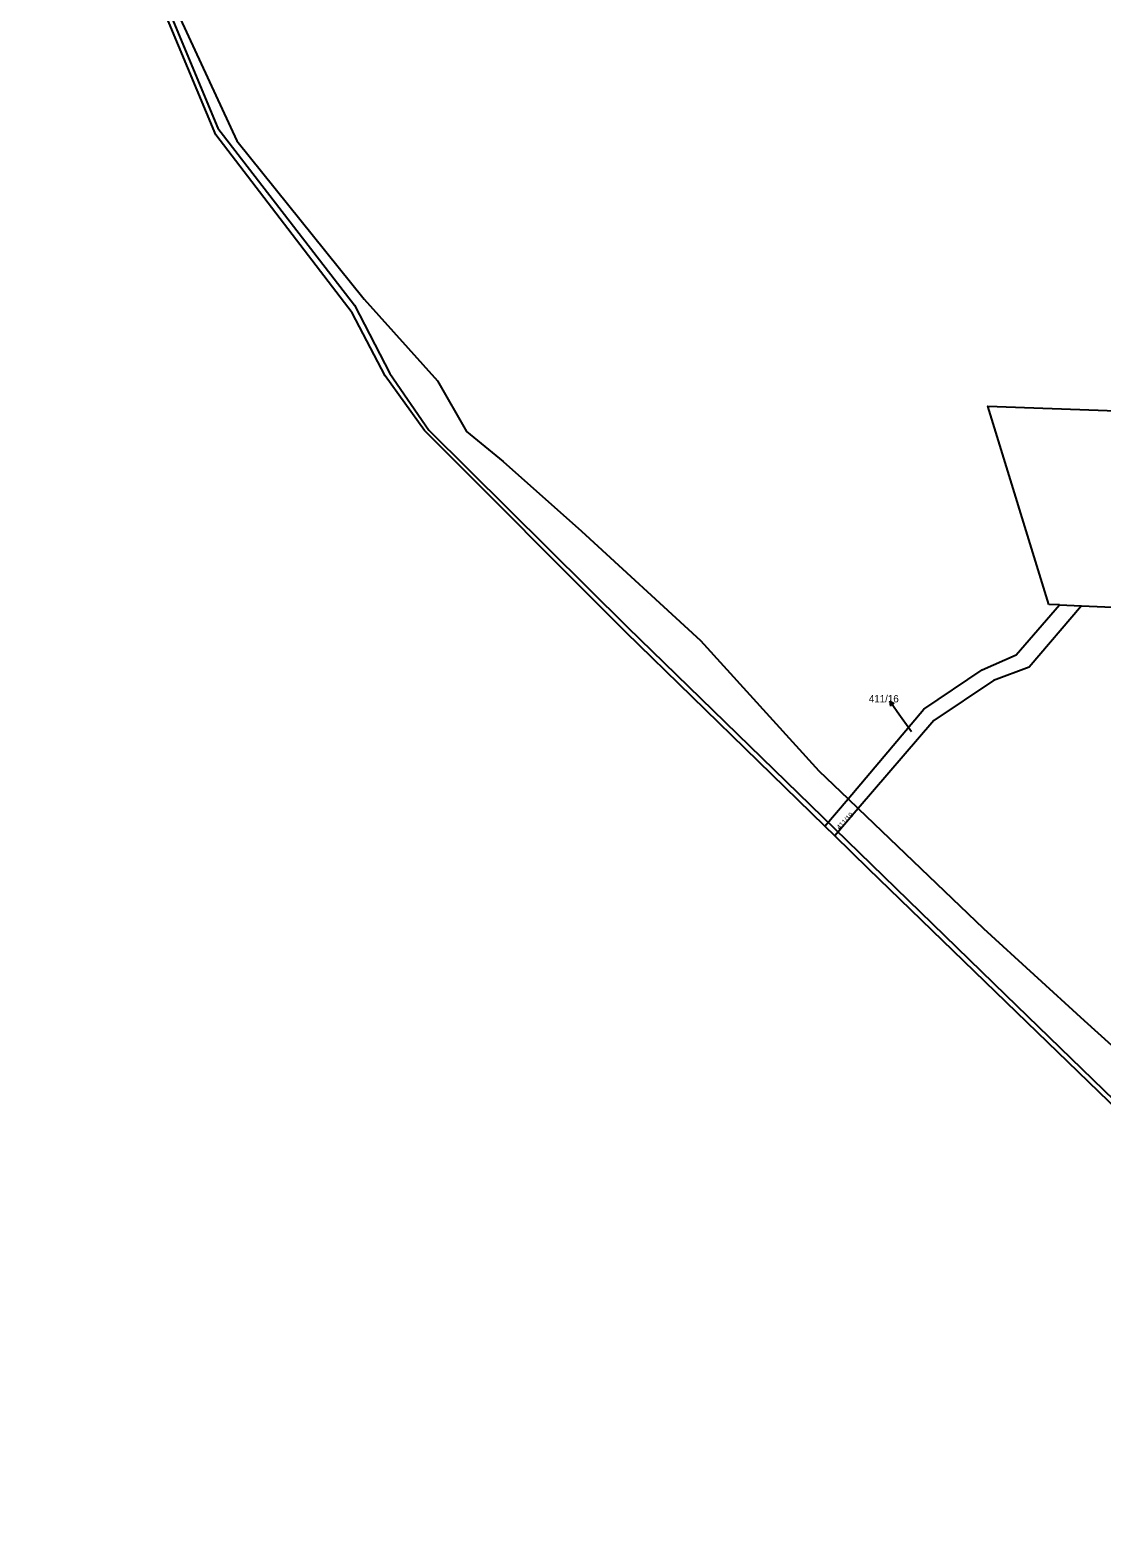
# Model space of a CAD drawing. Extents: x -880531 to -877616, y -1023932 to -1021350.
# Drawn here: x -880530.7 to -880281.2, y -1022570 to -1022219 of the extents above; entities that cross this region are included whole.
import ezdxf

# ---------------------------------------------------------------- set-up
doc = ezdxf.new("R2010")
doc.units = 0
for name, color, linetype in [('Hranice parcel', 7, 'Continuous'), ('Parcelní čísla', 7, 'Continuous'), ('Pop  PČ popisy', 7, 'Continuous'), ('Vnitřní kresba', 7, 'Continuous')]:
    doc.layers.add(name, color=color, linetype=linetype)

msp = doc.modelspace()

# ---------------------------------------------------------------- linework, layer by layer
at = {"layer": 'Hranice parcel'}
for p, q in [((-880391.99, -1022359.17), (-880438.9, -1022312.23)), ((-880291.06, -1022352.79), (-880293.53, -1022352.68)), ((-880291.06, -1022352.79), (-880285.88, -1022353.02)), ((-880285.88, -1022353.02), (-880196.77, -1022357.04)), ((-880345.66, -1022404.32), (-880391.99, -1022359.17)), ((-880347.08, -1022391.39), (-880340.26, -1022397.94)), ((-880345.66, -1022404.32), (-880340.26, -1022397.94)), ((-880337.9, -1022400.2), (-880343.36, -1022406.56)), ((-880340.26, -1022397.94), (-880337.9, -1022400.2)), ((-880337.9, -1022400.2), (-880308.75, -1022428.16)), ((-880343.36, -1022406.56), (-880345.66, -1022404.32)), ((-880335.48, -1022414.24), (-880343.36, -1022406.56))]:
    msp.add_line(p, q, dxfattribs=at)
for points in [[(-880438.9, -1022312.23), (-880448.03, -1022299.45), (-880455.75, -1022284.78), (-880487.48, -1022243.34), (-880524.79, -1022153.92), (-880529.34, -1022124.84), (-880530.7, -1022098.83), (-880528.56, -1022064.4), (-880524.89, -1022050.76), (-880519.28, -1022036.32), (-880479.95, -1021972.5), (-880463.94, -1021954.07), (-880458.37, -1021949.23)], [(-880452.22, -1021959.53), (-880469.68, -1021977.36), (-880478.53, -1021984.54), (-880491.76, -1022000.43), (-880511.96, -1022039.42), (-880517.25, -1022057.99), (-880520.93, -1022084.07), (-880523.46, -1022123.46), (-880519.31, -1022152.85), (-880508.5, -1022183.09), (-880495.79, -1022216.24), (-880482.58, -1022244.73), (-880452.91, -1022281.59), (-880435.85, -1022300.63), (-880429.09, -1022312.44), (-880420.6, -1022319.4), (-880402.34, -1022335.61), (-880374.63, -1022361.05), (-880347.08, -1022391.39)], [(-880293.53, -1022352.68), (-880307.71, -1022306.49), (-880237.11, -1022309.12), (-880176.85, -1022311.48)], [(-880340.26, -1022397.94), (-880322.65, -1022377.1), (-880309.06, -1022367.89), (-880301.11, -1022364.45), (-880291.06, -1022352.79)], [(-880285.88, -1022353.02), (-880298.14, -1022367.3), (-880306.43, -1022370.4), (-880320.3, -1022379.73), (-880337.9, -1022400.2)], [(-880234.6, -1022570), (-880234.38, -1022561.23), (-880236.2, -1022545.85), (-880242.27, -1022523.44), (-880253.08, -1022500.29), (-880261.13, -1022488.37), (-880272.31, -1022475.43), (-880300.95, -1022447.69), (-880335.48, -1022414.24)], [(-880308.75, -1022428.16), (-880285.32, -1022449.52), (-880263.77, -1022468.93), (-880224.44, -1022487.13), (-880146.12, -1022501.79)]]:
    msp.add_lwpolyline(points, dxfattribs=at)
at = {"layer": 'Pop  PČ popisy'}
for p, q in [((-880328.81, -1022377.7), (-880330.531, -1022375.242)), ((-880330.531, -1022375.242), (-880329.547, -1022375.775)), ((-880330.531, -1022375.242), (-880330.367, -1022376.349)), ((-880325.53, -1022382.35), (-880328.81, -1022377.7))]:
    msp.add_line(p, q, dxfattribs=at)
at = {"layer": 'Vnitřní kresba'}
for p, q in [((-880391.59, -1022357.95), (-880303.63, -1022443.58)), ((-880303.63, -1022443.58), (-880273.2, -1022473.11))]:
    msp.add_line(p, q, dxfattribs=at)
msp.add_lwpolyline([(-880517.86, -1022036.99), (-880523.75, -1022050.69), (-880527.41, -1022064.69), (-880529.64, -1022098.73), (-880528.21, -1022124.34), (-880523.98, -1022153.1), (-880487.02, -1022241.79), (-880455.17, -1022282.98), (-880446.92, -1022298.93), (-880437.86, -1022312.14), (-880391.59, -1022357.95)], dxfattribs=at)

# ---------------------------------------------------------------- texts
at = {"layer": 'Parcelní čísla'}
msp.add_text('411/16', height=1.7, dxfattribs=at).set_placement((-880335.426, -1022375.49))
msp.add_text('411/19', height=1.139, rotation=46, dxfattribs=at).set_placement((-880342.26, -1022405.229))

doc.saveas('drawing.dxf')
